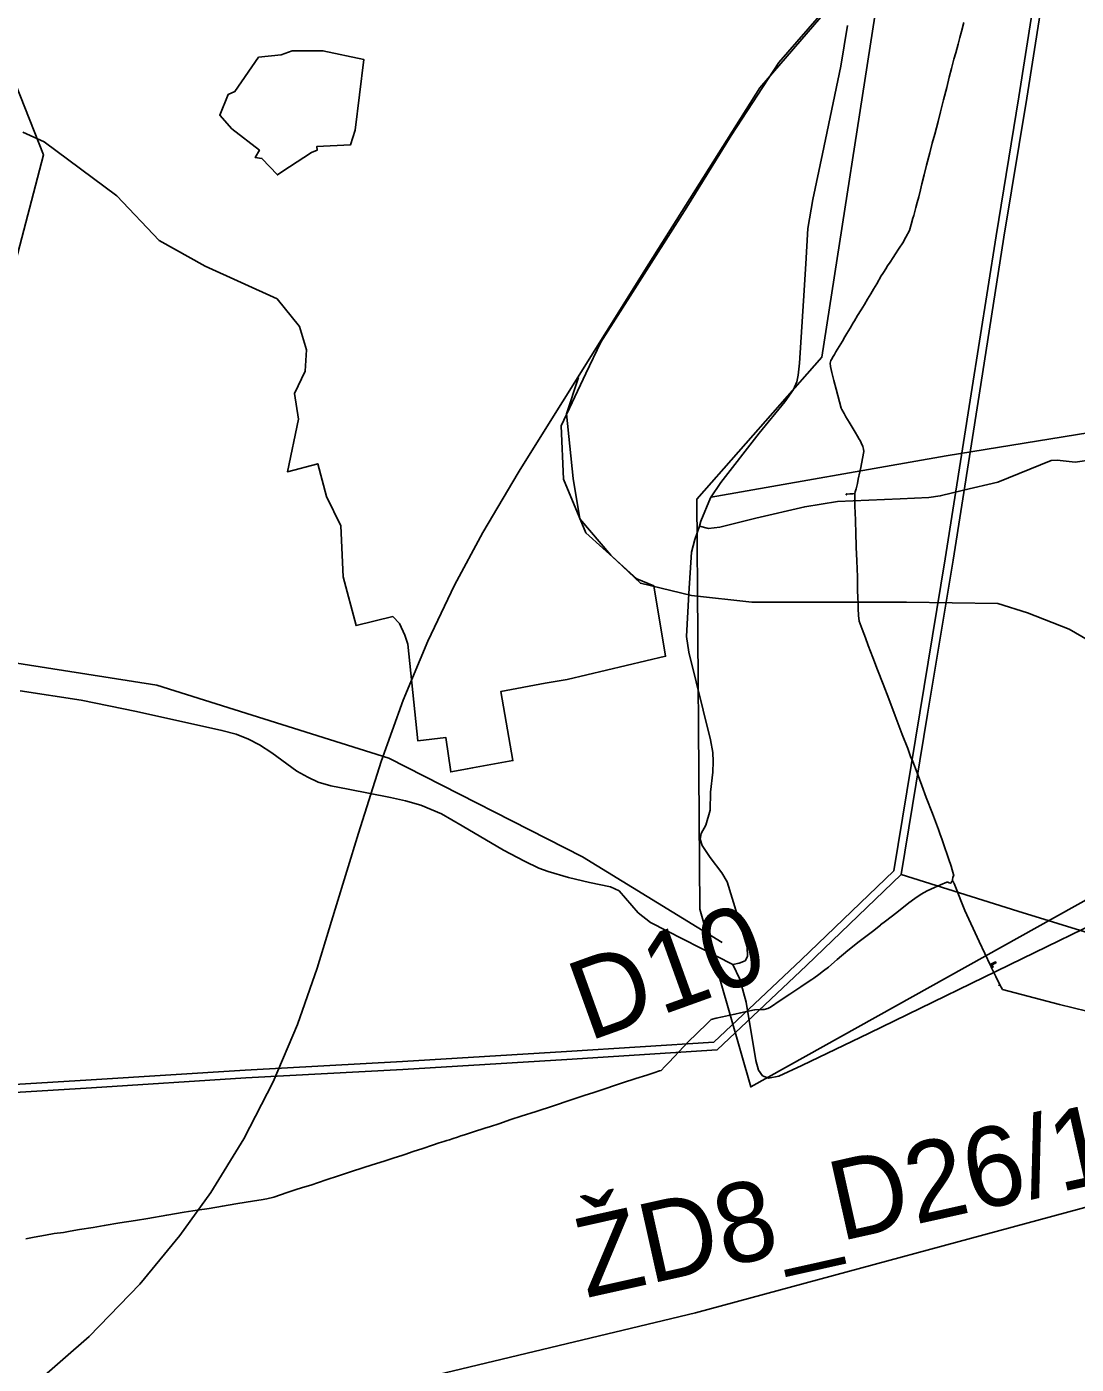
# Model space of a CAD drawing. Extents: x -789162 to -606354, y -1062736 to -945481.
# Drawn here: x -688746 to -686768, y -994659 to -992137 of the extents above; entities that cross this region are included whole.
import ezdxf

# ---------------------------------------------------------------- set-up
doc = ezdxf.new("R2010")
doc.units = 0
for name, color, linetype in [('_SIRSI VZTAHY_CYKLOTRASY MISTNI S', 7, 'Continuous'), ('_SIRSI VZTAHY_ELEKTRICKE VEDENI VN 110 kV S', 7, 'Continuous'), ('_SIRSI VZTAHY_OP vodnich zdroju II stupne', 7, 'Continuous'), ('_SIRSI VZTAHY_SILNICE I a II TRIDY_STAV POPIS', 7, 'Continuous'), ('_SIRSI VZTAHY_SILNICE III TRIDY_STAV', 7, 'Continuous'), ('_SIRSI VZTAHY_VTL PLYNOVOD', 7, 'Continuous'), ('_SIRSI VZTAHY_ZELEZNICE NAVRH', 7, 'Continuous'), ('_SIRSI VZTAHY_ZELEZNICE_NAVRH POPIS', 7, 'Continuous')]:
    doc.layers.add(name, color=color, linetype=linetype)

msp = doc.modelspace()

# ---------------------------------------------------------------- linework, layer by layer
at = {"layer": '_SIRSI VZTAHY_CYKLOTRASY MISTNI S'}
for points in [[(-687483.2, -993028.1), (-687247.3, -992760.3), (-687137.8, -992052), (-687156.9, -991261.1), (-687139.8, -990898.4), (-686941.4, -990528.8), (-686914.1, -990381.7), (-687339.8, -990115.4), (-687139.8, -989851.3), (-686992, -989932.1), (-686499.9, -989984.2), (-686422.9, -989699.9), (-686284.8, -989378.4), (-686007.6, -989239)], [(-688556.1, -989836.5), (-688904.9, -989942.6), (-689006.9, -990177.5), (-688990.4, -990418.2), (-688877.5, -990794.6), (-688784.4, -990982.2), (-688712.6, -991485.2), (-688781.8, -992007.3), (-688812.6, -992131.8), (-688714.4, -992378.9), (-688830.5, -992822.1), (-689079.5, -993178.6), (-688841.2, -993325.5), (-688500.5, -993378.6), (-688063.6, -993516.3), (-687698.6, -993702), (-687435.2, -993863.7)], [(-687456.1, -993024.3), (-687013.2, -992946.4), (-686498.6, -992862.6), (-686235.3, -993114.1), (-685816.3, -993191.9), (-685864.2, -993353.6), (-685690.7, -993455.4), (-685517.1, -993455.4), (-685433.3, -993102.1), (-685253.8, -993036.2), (-684661.3, -992670.9), (-684535.6, -992790.7), (-683781.6, -992335.6), (-683775.6, -992760.8), (-683195.1, -992383.5), (-682889.9, -992994.3), (-682866, -992760.8)], [(-684053.5, -995624.9), (-684491.2, -995009), (-684778.4, -995050.1), (-684949.4, -994827.6), (-685034.9, -995207.5), (-685534.2, -995217.7), (-685623.1, -994998.7), (-686119, -994820.8), (-686426.8, -994858.4), (-686720.9, -994796.8), (-686546.4, -994375.9), (-686577.2, -993920.8), (-686738, -993777.1), (-687381.5, -994136), (-687477.3, -993800.6), (-687483.2, -993028.1)]]:
    msp.add_lwpolyline(points, dxfattribs=at)
at = {"layer": '_SIRSI VZTAHY_ELEKTRICKE VEDENI VN 110 kV S'}
for points in [[(-687451.1, -994051.8), (-687286.8, -993896.2), (-687112.2, -993728.6), (-687063.1, -993431), (-687015, -993140.6), (-686965.9, -992829.5), (-686919.2, -992531.6), (-686876.3, -992269.3), (-686827.9, -991961.7), (-686779.6, -991659.8), (-686736, -991384.3), (-686689.8, -991092.6), (-686599, -990821.5), (-686501.5, -990524.6), (-686415.2, -990261.5), (-686321.1, -989977.3), (-686243.1, -989742.1), (-686159.3, -989488), (-686062.1, -989191.4), (-685979.1, -988943.5), (-685905.5, -988720.6), (-685829.4, -988490.2), (-685756.3, -988268), (-685732.3, -988002.4)], [(-687098.1, -993735.7), (-687048.3, -993433.5), (-687000.2, -993143.1), (-686951.1, -992831.9), (-686904.4, -992534.1), (-686861.5, -992271.8), (-686813.1, -991964.1), (-686764.8, -991662.2), (-686721.2, -991386.8), (-686675.2, -991096.1), (-686584.8, -990826.2), (-686487.3, -990529.2), (-686401, -990266.2), (-686306.9, -989982), (-686228.9, -989746.8), (-686145, -989492.7), (-686047.8, -989196.2), (-685964.9, -988948.3), (-685891.3, -988725.2), (-685815.2, -988494.8), (-685741.5, -988271.1), (-685717.4, -988003.3)], [(-687444.6, -994066.3), (-687276.3, -993906.9), (-687098.1, -993735.7)], [(-686335.6, -993890.5), (-686484.1, -993882.5), (-686643.8, -993877.1), (-686878.4, -993804.9), (-687098.1, -993735.7)], [(-691328.6, -994287.5), (-691060.1, -994272.1), (-690775.8, -994252.4), (-690466.8, -994234.3), (-690164.9, -994214.5), (-689852.6, -994195.3), (-689543.6, -994178.3), (-689246.9, -994160.9), (-688935, -994141.8), (-688624.4, -994122.5), (-688334, -994104.2), (-688038, -994088), (-687728.8, -994069.1), (-687451.1, -994051.8)], [(-691327.7, -994302.5), (-691059.2, -994287.1), (-690774.9, -994267.4), (-690465.9, -994249.3), (-690164, -994229.5), (-689851.6, -994210.2), (-689542.7, -994193.3), (-689246, -994175.9), (-688934.1, -994156.8), (-688623.6, -994137.5), (-688333.1, -994119.1), (-688037.1, -994103), (-687727.9, -994084), (-687444.6, -994066.3)]]:
    msp.add_lwpolyline(points, dxfattribs=at)
at = {"layer": '_SIRSI VZTAHY_OP vodnich zdroju II stupne'}
msp.add_lwpolyline([(-688753.4, -992336.2), (-688712.8, -992354.3), (-688576.1, -992456.4), (-688496.5, -992540.6), (-688409.4, -992588.7), (-688274.1, -992650.3), (-688232.1, -992702.8), (-688218.5, -992746.4), (-688221.5, -992787), (-688241.1, -992829.1), (-688233.6, -992877.1), (-688254.6, -992976.3), (-688197.5, -992961.3), (-688181, -993022.9), (-688153.9, -993078.5), (-688149.4, -993174.6), (-688125.4, -993266.3), (-688055.9, -993249.4), (-688043.7, -993262.1), (-688033.4, -993284.1), (-688028, -993301.3), (-688009.2, -993483.5), (-687956.2, -993477), (-687946.9, -993542.1), (-687915.5, -993536.3), (-687905.6, -993534.5), (-687829.8, -993520.7), (-687852.5, -993390.8), (-687769, -993374.9), (-687727.5, -993368.2), (-687542, -993324.2), (-687564.2, -993191.1), (-687596.4, -993178.4), (-687692.6, -993091.3), (-687734.6, -992990.6), (-687739.1, -992890), (-687692.6, -992790.8), (-687664.1, -992731.8), (-687599.9, -992631.4), (-687501.9, -992477.3), (-687418.5, -992342.4), (-687328.5, -992205.1), (-687239.4, -992102.3)], dxfattribs=at)
for points in [[(-688359.3, -992329.9), (-688382.1, -992303.8), (-688366.4, -992265.2), (-688353.6, -992259.3), (-688308.9, -992194.7), (-688266.3, -992190.4), (-688245.9, -992183.1), (-688187.8, -992182.6), (-688110.8, -992199.1), (-688127, -992332.3), (-688135.5, -992359.8), (-688199.1, -992363.1), (-688198.6, -992370.3), (-688209.1, -992374.5), (-688223.5, -992383.9), (-688263.3, -992409.9), (-688273.6, -992416.6), (-688302.6, -992385.6), (-688315.2, -992384.2), (-688307.5, -992370.1)], [(-688353.6, -992259.3), (-688366.4, -992265.2), (-688382.1, -992303.8), (-688359.3, -992329.9), (-688307.5, -992370.1), (-688315.2, -992384.2), (-688302.6, -992385.6), (-688273.6, -992416.6), (-688263.3, -992409.9), (-688223.5, -992383.9), (-688209.1, -992374.5), (-688198.6, -992370.3), (-688199.1, -992363.1), (-688135.5, -992359.8), (-688127, -992332.3), (-688110.8, -992199.1), (-688187.8, -992182.6), (-688245.9, -992183.1), (-688266.3, -992190.4), (-688308.9, -992194.7)]]:
    msp.add_lwpolyline(points, close=True, dxfattribs=at)
at = {"layer": '_SIRSI VZTAHY_SILNICE III TRIDY_STAV'}
for points in [[(-687199.1, -992135.2), (-687211.5, -992211.6), (-687246.6, -992376.7), (-687264.6, -992463.4), (-687273.7, -992517.5), (-687277.5, -992584.6), (-687282.4, -992654.4), (-687289.4, -992771.5), (-687292, -992794.3), (-687294.6, -992806.7), (-687300.8, -992821), (-687317.5, -992844.5), (-687365.4, -992903.8), (-687438, -992996.7), (-687457.1, -993025.6), (-687475.3, -993069.4), (-687478.3, -993079)], [(-687478.3, -993079), (-687460.9, -993083.4), (-687439.9, -993080.5), (-687371.7, -993063.7), (-687279.9, -993042.4), (-687218.2, -993032.7), (-687099.9, -993027.2), (-687046.2, -993025), (-687024.4, -993021.8), (-686980.4, -993010.8), (-686916.1, -992996.1), (-686815.5, -992955.4), (-686803.9, -992954.6), (-686770.1, -992958.3), (-686735.5, -992953.5)], [(-687478.3, -993079), (-687487, -993104.1), (-687493.1, -993127.8), (-687498, -993206.1), (-687502.8, -993287.2), (-687498.3, -993316.2), (-687457.7, -993481.4), (-687453.3, -993505.6), (-687452.3, -993522.8), (-687452.7, -993542.5), (-687457.1, -993580.2), (-687458.2, -993614.5), (-687466.3, -993642.3), (-687474.8, -993658.3), (-687476.7, -993668.8), (-687472.9, -993681.2), (-687457.8, -993703.5), (-687435.9, -993732.5), (-687425.9, -993749.6), (-687388.4, -993872.5), (-687387.8, -993889.9), (-687392.2, -993898.1), (-687403.6, -993903), (-687415.4, -993905.3)], [(-688758.1, -993389.2), (-688643.2, -993407.2), (-688539.1, -993428.1), (-688378.1, -993464), (-688351.4, -993471.3), (-688328, -993480.5), (-688307, -993491), (-688284.1, -993506), (-688236.8, -993540.5), (-688216.5, -993551.9), (-688196.5, -993561.6), (-688173, -993568.5), (-688140.4, -993574.8), (-688060.3, -993590.7), (-688032.4, -993596.7), (-688003.4, -993604.8), (-687964.2, -993621.1), (-687925.5, -993644), (-687847.2, -993689.4), (-687807.6, -993710.4), (-687780.9, -993723.7), (-687763, -993730.1), (-687724.7, -993740.9), (-687685.6, -993750.4), (-687645.6, -993759), (-687629.8, -993766.6), (-687593.5, -993807.6), (-687570.5, -993826.1), (-687415.4, -993905.3)], [(-687415.4, -993905.3), (-687401.9, -993933.1), (-687390.1, -993976), (-687372.2, -994086.1), (-687367.1, -994104.2), (-687359.1, -994115.2), (-687347.9, -994119.3), (-687328.4, -994116), (-687285, -994095.5), (-687158.7, -994034.9), (-686846.1, -993882.8), (-686732.7, -993827.1)]]:
    msp.add_lwpolyline(points, dxfattribs=at)
at = {"layer": '_SIRSI VZTAHY_VTL PLYNOVOD'}
for points in [[(-687185.3, -993017.6), (-687184.8, -993014.4), (-687183.1, -993008.5), (-687180.6, -992998.2), (-687179, -992990.3), (-687176, -992976.4), (-687174.3, -992968.4), (-687171, -992951.6), (-687168.6, -992938), (-687168.8, -992933.7), (-687170.1, -992928.5), (-687173.3, -992922), (-687175.5, -992917.7), (-687177.4, -992914.8), (-687180.7, -992909.1), (-687185.1, -992901.7), (-687190.6, -992892.3), (-687196.4, -992882.8), (-687202.5, -992872.9), (-687205.7, -992866.5), (-687210, -992858.9), (-687211, -992856.6), (-687220.4, -992820.7), (-687224.7, -992804.1), (-687228.6, -992789.3), (-687231.5, -992778.1), (-687231.6, -992771.9), (-687231.3, -992769.4), (-687230.7, -992766.7), (-687229.6, -992764.4), (-687226.2, -992759.3), (-687223.7, -992755.4), (-687221, -992750.3), (-687217.8, -992745.3), (-687215, -992740.5), (-687208.7, -992730.4), (-687204.1, -992722), (-687200.5, -992715.8), (-687194.2, -992705.9), (-687188.6, -992695.8), (-687186, -992691.6), (-687180.3, -992681.9), (-687173.7, -992671.3), (-687167.2, -992661.1), (-687161.4, -992651), (-687155, -992640.8), (-687150.4, -992632.2), (-687144, -992621.9), (-687135.5, -992607.2), (-687132.5, -992602.3), (-687126, -992592), (-687124.5, -992588.8), (-687120.2, -992582.8), (-687111.9, -992570.4), (-687109.8, -992567.4), (-687101.8, -992554.9), (-687095.1, -992544.7), (-687089.2, -992534.3), (-687082.2, -992521.7), (-687079.4, -992510.3), (-687075.9, -992498.2), (-687074.5, -992493.1), (-687070.6, -992478.3), (-687068, -992469), (-687065, -992458), (-687061.6, -992444.9), (-687059, -992433.6), (-687054.8, -992416.3), (-687050.1, -992398.5), (-687044.2, -992375.2), (-687039.4, -992356.9), (-687034.9, -992339.7), (-687028.5, -992316.2), (-687023.7, -992298.1), (-687018.2, -992275.3), (-687012, -992251.7), (-687007.4, -992232.5), (-687003.1, -992216.3), (-686998.6, -992198.5), (-686995.3, -992186.5), (-686990.9, -992170.4), (-686987.6, -992157.5), (-686984.4, -992146.1), (-686979.9, -992129.2)], [(-687201.5, -993020.5), (-687201.5, -993020.4), (-687201.4, -993019.9), (-687201.5, -993019.7), (-687201.5, -993019.6), (-687201.5, -993019.1), (-687201.5, -993018.8), (-687201.5, -993018.7), (-687201.4, -993018.6), (-687201, -993018.5), (-687200.9, -993018.5)], [(-687200.3, -993018.5), (-687200.3, -993018.1), (-687200.5, -993018.1), (-687200.8, -993018.2), (-687200.9, -993018.2), (-687200.9, -993018.5)], [(-687200.9, -993018.5), (-687200.6, -993018.5), (-687200.3, -993018.5)], [(-687200.3, -993018.5), (-687200.1, -993018.5), (-687194.7, -993018.2), (-687189.2, -993017.8), (-687186.5, -993017.6), (-687186.3, -993017.6), (-687185.4, -993017.6), (-687185.3, -993017.6)], [(-687000.6, -993748.1), (-687001.4, -993746.9), (-687001.2, -993745.3), (-687000.7, -993740.6), (-686999, -993737.6), (-686999.7, -993735.8), (-687000.6, -993730.9), (-687003.2, -993722.1), (-687003.3, -993721.6), (-687009.3, -993703.3), (-687017.4, -993679.6), (-687021.6, -993668.6), (-687024.7, -993660.4), (-687027.8, -993650.6), (-687039.3, -993620.7), (-687051, -993590.2), (-687059.4, -993567.5), (-687067.9, -993544), (-687076.2, -993522.8), (-687080.3, -993513.4), (-687082.3, -993507.4), (-687085.7, -993498.1), (-687096.1, -993471.6), (-687109.5, -993436.4), (-687121.6, -993404.4), (-687132.1, -993376.7), (-687142.5, -993349.5), (-687151.3, -993326.7), (-687160, -993303.8), (-687165.5, -993289.1), (-687171.6, -993273.1), (-687175.3, -993263.2), (-687177.1, -993258.3), (-687178.5, -993247.2), (-687179.3, -993234.1), (-687179.2, -993228.1), (-687179.7, -993210.5), (-687180.1, -993203.3), (-687180.6, -993174.7), (-687181.9, -993144), (-687182.9, -993118.3), (-687183.8, -993090.4), (-687184.3, -993071.6), (-687185.1, -993050.1), (-687185.3, -993044.7), (-687185.3, -993044.5), (-687185.3, -993044.5), (-687185.3, -993044.2), (-687185.2, -993040.5), (-687185.2, -993039.1), (-687185.2, -993038.8), (-687185.7, -993024), (-687185.7, -993023.9), (-687185.5, -993020.3), (-687185.4, -993019.2), (-687185.4, -993018.3), (-687185.3, -993018), (-687185.3, -993017.6)], [(-688747.8, -994422.4), (-688731.9, -994419.5), (-688710.7, -994415.7), (-688694, -994412.6), (-688676.7, -994410.3), (-688670.6, -994409.2), (-688664.1, -994408), (-688646.5, -994404.9), (-688620.8, -994400.8), (-688599.7, -994397.5), (-688570.6, -994392.5), (-688541.1, -994387.6), (-688517.9, -994383.9), (-688482, -994377.6), (-688449, -994372.4), (-688425, -994368.4), (-688401.9, -994365.1), (-688377.1, -994360.6), (-688352, -994356.6), (-688317, -994351), (-688304.3, -994349.1), (-688293.3, -994346.9), (-688280.4, -994343.9), (-688255.4, -994335.3), (-688236.3, -994328.9), (-688222.1, -994324.3), (-688210.8, -994321), (-688181.5, -994311.3), (-688158.6, -994303.4), (-688131.8, -994294.9), (-688095.2, -994282.8), (-688072.6, -994275.7), (-688053.5, -994269.8), (-688039.3, -994265), (-688033.6, -994263.2), (-688017.5, -994257.8), (-687999.2, -994251.8), (-687981.1, -994245.8), (-687968.7, -994241.4), (-687960.2, -994239), (-687954.5, -994237.3), (-687949.5, -994235.5), (-687942.4, -994233.5), (-687934, -994230.7), (-687927.6, -994228.5), (-687920.9, -994226.5), (-687903.7, -994220.8), (-687882.6, -994213.9), (-687871.9, -994210.5), (-687856.4, -994205.4), (-687833.8, -994197.6), (-687813.9, -994191.2), (-687786, -994182.1), (-687753.1, -994171.5), (-687721.6, -994161), (-687695.6, -994152.4), (-687677.1, -994146.3), (-687650.6, -994137.5), (-687642.1, -994134.7), (-687642.1, -994134.7), (-687623.3, -994128.5), (-687597.8, -994120.1), (-687577.5, -994113.6), (-687564.3, -994109.2), (-687553.3, -994105.8), (-687550.6, -994105.2), (-687543.2, -994097.6), (-687535.4, -994089.5), (-687517.1, -994069.9), (-687500.2, -994051.7), (-687482.8, -994034.6), (-687463.6, -994016.2), (-687456.2, -994008.9), (-687446.9, -994006.7), (-687434.9, -994003.9), (-687423.2, -994001.4), (-687411.3, -993998.9), (-687400.7, -993996.4), (-687392, -993994.2), (-687383.4, -993992.7), (-687374.3, -993990.7), (-687373.9, -993990.6), (-687360.9, -993990.3), (-687357.9, -993990.3), (-687356, -993990.3), (-687349.2, -993988.3), (-687344.6, -993985.5), (-687326.1, -993973.3), (-687307.9, -993961.4), (-687287.4, -993947.6), (-687277.1, -993940.7), (-687266.7, -993933.6), (-687262.6, -993931), (-687253, -993924), (-687244.3, -993917.2), (-687235.3, -993910), (-687218.5, -993895.9), (-687198.5, -993879.1), (-687177.2, -993862.1), (-687152.4, -993842.9), (-687137.2, -993830.8), (-687137.1, -993830.7), (-687127.7, -993823.5), (-687106.2, -993807), (-687083.7, -993789.2), (-687072.3, -993780.6), (-687060.3, -993772.4), (-687048.9, -993766.6), (-687035.5, -993760.1), (-687023.7, -993755.2), (-687011.9, -993749.9), (-687010.3, -993749.9), (-687007.4, -993751.2), (-687005.1, -993751.7), (-687003.8, -993751.2), (-687003.4, -993750.6), (-687003.2, -993749.7), (-687003.2, -993749.7), (-687003, -993749.6)], [(-687003, -993749.6), (-687003.4, -993749), (-687003.2, -993748.8), (-687002.9, -993748.6), (-687002.6, -993748.4), (-687002.4, -993748.2), (-687001.9, -993748.7)], [(-687003, -993749.6), (-687002.8, -993749.4), (-687002.6, -993749.2), (-687002.5, -993749.1), (-687002.1, -993748.9), (-687001.9, -993748.7)], [(-687001.9, -993748.7), (-687001.8, -993748.6), (-687000.6, -993748.1)], [(-686929.7, -993907.3), (-686929.9, -993906.9), (-686950.9, -993862), (-686977.9, -993803.5), (-686984.2, -993787.9), (-686994.6, -993762.1), (-686998.5, -993752.5), (-686998.5, -993752.5), (-686998.6, -993752.2), (-686999.7, -993749.6), (-687000.6, -993748.1)], [(-686929.2, -993908.4), (-686928.4, -993908), (-686928.3, -993908), (-686928.7, -993907.5), (-686928.8, -993907), (-686929, -993907.1), (-686929.7, -993907.3)], [(-686929.2, -993908.4), (-686929.5, -993907.7), (-686929.7, -993907.3)], [(-686928.2, -993910.7), (-686929.2, -993908.4)], [(-686926.7, -993903.2), (-686928.4, -993904.1), (-686927.3, -993906.4), (-686925.9, -993909.5), (-686928.2, -993910.7)], [(-686927.9, -993911.4), (-686928, -993911.1), (-686928.2, -993910.7)], [(-686927.9, -993911.4), (-686924.9, -993910), (-686925.8, -993907.8), (-686926.2, -993907), (-686926.7, -993905.9), (-686924.1, -993904.5), (-686923.4, -993904.1)], [(-686912.3, -993943.1), (-686919.4, -993928.2), (-686919.5, -993927.9), (-686927.3, -993912.6), (-686927.9, -993911.4)], [(-686924.2, -993901.9), (-686924.4, -993902), (-686925.2, -993902.4), (-686926.7, -993903.2)], [(-686926.7, -993903.2), (-686926.2, -993904), (-686923.8, -993902.8)], [(-686922.3, -993903.6), (-686921.6, -993903.2), (-686919.5, -993902.1), (-686920.6, -993900), (-686924.2, -993901.9)], [(-686923.8, -993902.8), (-686924.2, -993901.9)], [(-686923.8, -993902.8), (-686922.9, -993902.3), (-686922.5, -993903.1), (-686922.3, -993903.6)], [(-686923.4, -993904.1), (-686923.4, -993903.7), (-686923.8, -993902.8)], [(-686923.4, -993904.1), (-686922.6, -993903.8), (-686922.3, -993903.6)], [(-686913.8, -993944.3), (-686914, -993944), (-686913.5, -993943.7), (-686912.5, -993943.2), (-686912.3, -993943.1)], [(-686913.8, -993944.3), (-686914, -993944.5)], [(-686912.1, -993943.5), (-686912.8, -993943.9), (-686913, -993943.9), (-686913.8, -993944.3)], [(-686912.1, -993943.5), (-686912.3, -993943.1)], [(-686363.7, -994339.2), (-686363.9, -994322.3), (-686363, -994307.5), (-686365, -994271.9), (-686397.9, -994242.9), (-686468.5, -994176.4), (-686472.9, -994172.3), (-686472.9, -994172.2), (-686473.9, -994171.3), (-686485.5, -994159.4), (-686498.1, -994143.7), (-686510.7, -994129.1), (-686522.2, -994115.7), (-686535.7, -994100.8), (-686554.9, -994079.8), (-686572.8, -994060.6), (-686603.2, -994027.9), (-686618.9, -994025.1), (-686630.3, -994021.8), (-686630.6, -994021.7), (-686722.3, -993999.6), (-686800, -993980.8), (-686907.1, -993952.3), (-686912.1, -993943.5)]]:
    msp.add_lwpolyline(points, dxfattribs=at)
at = {"layer": '_SIRSI VZTAHY_ZELEZNICE NAVRH'}
for points in [[(-686795.8, -991462.7), (-686873.2, -991644.1), (-686977.6, -991797.7), (-687174.2, -992031.1), (-687364.7, -992252.3), (-687573.6, -992584.1), (-687816, -992972.3), (-687819.7, -992978.2), (-687886.7, -993090.9), (-687939.6, -993190.2), (-687989.9, -993295.9), (-688036.3, -993406.7), (-688078.3, -993522.7), (-688120.9, -993657.6), (-688164.5, -993801), (-688198.7, -993911.9), (-688235.7, -994018.6), (-688281.7, -994126.7), (-688337, -994233.6), (-688399.2, -994334.8), (-688457.1, -994415.8), (-688533, -994508.1), (-688628.5, -994606.8), (-688727.7, -994693.5)], [(-685383.4, -994281.2), (-685910.1, -993887.2), (-686398.9, -993555.2), (-686681.4, -993331.1), (-686781.8, -993272.8), (-686860.3, -993242.4), (-686916, -993224.6), (-687088.2, -993222.1), (-687214.8, -993222.1), (-687379.4, -993222.1), (-687493.4, -993209.4), (-687589.6, -993186.6), (-687645.3, -993133.4), (-687703.6, -993065), (-687716.2, -992988.9), (-687728.9, -992867.3), (-687706.1, -992798.9)], [(-686682.5, -994344.6), (-687485.4, -994561.6), (-688457.9, -994794.7), (-689372.2, -995027.4)]]:
    msp.add_lwpolyline(points, dxfattribs=at)

# ---------------------------------------------------------------- texts
at = {"layer": '_SIRSI VZTAHY_SILNICE I a II TRIDY_STAV POPIS'}
msp.add_text('D10', height=150, rotation=19.8112, dxfattribs=at).set_placement((-687687.3, -994050.6))
at = {"layer": '_SIRSI VZTAHY_ZELEZNICE_NAVRH POPIS'}
msp.add_text('ŽD8_D26/1', height=150, rotation=12.6033, dxfattribs=at).set_placement((-687691.8, -994534.2))

doc.saveas('drawing.dxf')
